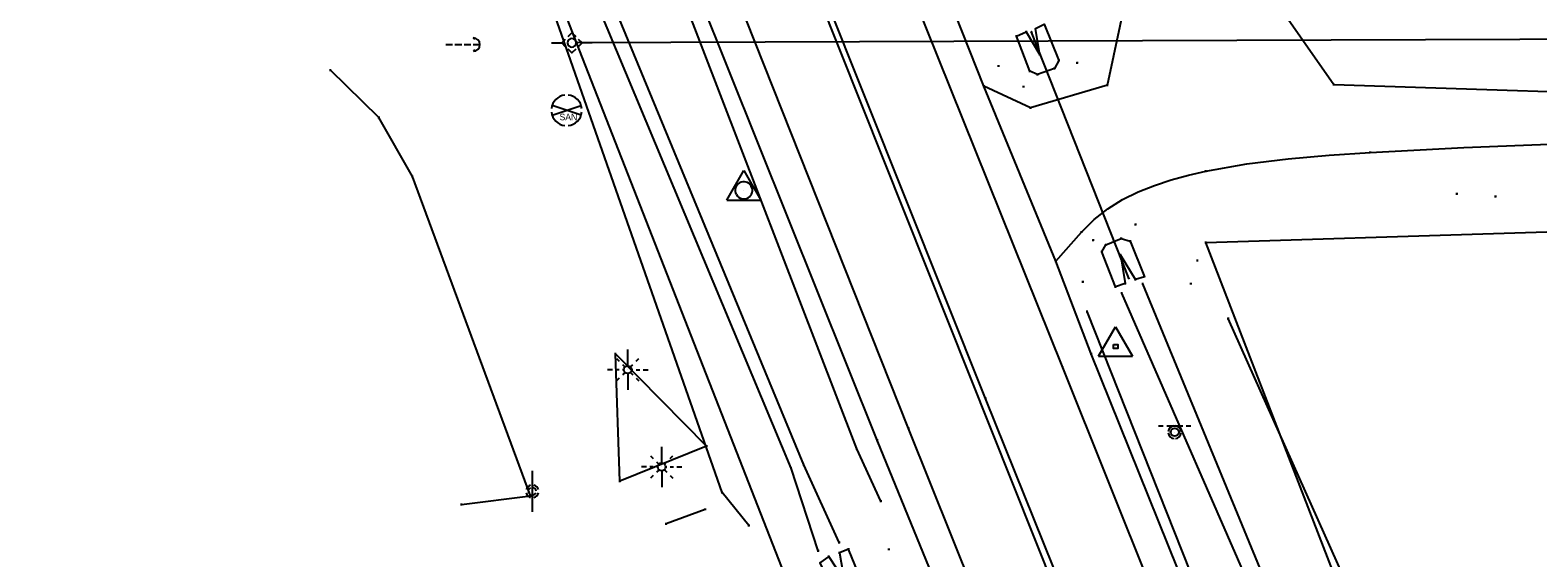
# Model space of a CAD drawing. Extents: x 1954856 to 2011933, y 399149 to 426294.
# Drawn here: x 2004038.2 to 2004259.6, y 409894.5 to 409972 of the extents above; entities that cross this region are included whole.
import ezdxf

# ---------------------------------------------------------------- set-up
doc = ezdxf.new("R2010")
doc.units = 0
for name, color, linetype in [('BankMent_ep', 7, 'Continuous'), ('BaselineSurvey', 7, 'Continuous'), ('Driveway_ep', 7, 'Continuous'), ('ElecAer_ep', 7, 'Continuous'), ('EndTreatMES_ep', 7, 'Continuous'), ('Fence_ep', 7, 'Continuous'), ('FlowLineInvert_ep', 7, 'Continuous'), ('GuyWireAnchor_ep', 7, 'Continuous'), ('MonumentIRC_ep', 7, 'Continuous'), ('MonumentNL_ep', 7, 'Continuous'), ('PavtAsphalt_ep', 7, 'Continuous'), ('PavtAsphaltCrown_ep', 7, 'Continuous'), ('PipeCulvert_ep', 7, 'Continuous'), ('PointLocator_ep', 7, 'Continuous'), ('PoleShared_ep', 7, 'Continuous'), ('ShldrPaved_ep', 7, 'Continuous'), ('SignMulti_ep', 7, 'Continuous'), ('SignSingle_ep', 7, 'Continuous'), ('Sprinkler_ep', 7, 'Continuous'), ('TopoMisc_ep', 7, 'Continuous'), ('TreeLineWoods_ep', 7, 'Continuous'), ('ValveCvrSewer_ep', 7, 'Continuous'), ('WaterFct_ep', 7, 'Continuous')]:
    doc.layers.add(name, color=color, linetype=linetype)

msp = doc.modelspace()

# ---------------------------------------------------------------- linework, layer by layer
at = {"layer": 'BankMent_ep'}
for p, q in [((2004159.58, 409910.52), (2004123.48, 410004.36)), ((2004139.82, 409904.12), (2004107.03, 409997.81)), ((2004232.82, 409831.42), (2004193.41, 409930.68)), ((2004254.24, 409839.9), (2004214.14, 409929.67)), ((2004163.13, 409902.84), (2004159.58, 409910.52)), ((2004143.75, 409899.27), (2004139.82, 409904.12))]:
    msp.add_line(p, q, dxfattribs=at)
for points in [[(2004157.02, 409896.76), (2004151.8, 409908.19), (2004113.49, 410000.86), (2004094.88, 410060.4)], [(2004153.92, 409895.54), (2004149.96, 409907.7), (2004111.48, 409999.81), (2004091.05, 410059.29)], [(2004319.2, 409650.34), (2004281.73, 409743.33), (2004242.69, 409835.04), (2004201.58, 409934.74)], [(2004316.4, 409649.26), (2004278.79, 409741.78), (2004241.68, 409834.55), (2004198.51, 409933.41)]]:
    msp.add_lwpolyline(points, dxfattribs=at)
at = {"layer": 'BaselineSurvey'}
msp.add_line((2004967.71, 407935.04), (2004043.6, 410254.04), dxfattribs=at)
msp.add_line((2004967.71, 407935.04), (2004043.6, 410254.04), dxfattribs=at)
at = {"layer": 'Driveway_ep'}
for p, q in [((2004229.64, 409964), (2004211, 409990.58)), ((2004196.39, 409963.92), (2004201.2, 409986.46)), ((2004188.82, 409938.07), (2004192.59, 409942.35))]:
    msp.add_line(p, q, dxfattribs=at)
for points in [[(2004196.39, 409963.92), (2004185.12, 409960.58), (2004178.25, 409963.76)], [(2004343.45, 409960.26), (2004229.64, 409964)], [(2004192.59, 409942.35), (2004194.43, 409944.19), (2004196.45, 409945.77), (2004198.62, 409947.12), (2004200.91, 409948.26), (2004203.31, 409949.22), (2004205.77, 409950.03), (2004208.29, 409950.71), (2004210.82, 409951.29), (2004216.88, 409952.38), (2004222.92, 409953.13), (2004228.95, 409953.65), (2004234.98, 409954.04), (2004248.72, 409954.77), (2004262.49, 409955.3), (2004276.29, 409955.58), (2004290.12, 409955.59), (2004303.98, 409955.28), (2004317.85, 409954.61), (2004331.74, 409953.53), (2004345.64, 409952.02)]]:
    msp.add_lwpolyline(points, dxfattribs=at)
at = {"layer": 'ElecAer_ep'}
for points in [[(2004118.46, 409970.19), (2004017.81, 410228.92), (2003963.49, 410214.77)], [(2004235.16, 409671.95), (2004118.46, 409970.19), (2004326.19, 409970.93)]]:
    msp.add_lwpolyline(points, dxfattribs=at)
at = {"layer": 'EndTreatMES_ep'}
for points in [[(2004183.04, 409971.1), (2004184.47, 409971.75), (2004186.49, 409968.39), (2004185.86, 409972.26), (2004187.12, 409972.87), (2004189.27, 409967.55), (2004188.62, 409966.38), (2004186.13, 409965.48), (2004184.99, 409965.99)], [(2004195.58, 409939.47), (2004196.17, 409940.48), (2004198.42, 409941.4), (2004199.73, 409941), (2004201.83, 409935.81), (2004200.51, 409935.38), (2004198.3, 409939), (2004199.01, 409934.8), (2004197.57, 409934.31)], [(2004160.76, 409889.94), (2004158.39, 409895.82), (2004157.04, 409895.25), (2004157.73, 409891.31), (2004155.47, 409894.72), (2004154.19, 409893.82), (2004156.77, 409888.36)]]:
    msp.add_lwpolyline(points, close=True, dxfattribs=at)
at = {"layer": 'Fence_ep'}
msp.add_lwpolyline([(2004101.56, 409902.35), (2004111.69, 409903.61), (2004094.35, 409950.5), (2004089.44, 409959.16), (2004082.31, 409966.12)], dxfattribs=at)
at = {"layer": 'FlowLineInvert_ep'}
for p, q in [((2004185.33, 409971.64), (2004185.15, 409971.81)), ((2004185.33, 409971.81), (2004185.15, 409971.64)), ((2004185.24, 409971.72), (2004185.24, 409971.72)), ((2004199.63, 409935.49), (2004199.46, 409935.66)), ((2004199.63, 409935.66), (2004199.46, 409935.49)), ((2004199.55, 409935.57), (2004199.55, 409935.57))]:
    msp.add_line(p, q, dxfattribs=at)
at = {"layer": 'GuyWireAnchor_ep'}
for p, q in [((2004099.26, 409969.89), (2004100.26, 409969.89)), ((2004100.6, 409969.89), (2004101.6, 409969.89)), ((2004101.93, 409969.89), (2004102.93, 409969.89)), ((2004103.26, 409969.88), (2004104.26, 409969.88)), ((2004103.29, 409970.86), (2004103.48, 409970.66)), ((2004104.26, 409969.88), (2004104.26, 409969.88)), ((2004103.31, 409968.91), (2004103.54, 409969.14))]:
    msp.add_line(p, q, dxfattribs=at)
msp.add_arc((2004103.29, 409969.88), 0.973, 271.14, 90.0059, dxfattribs=at)
at = {"layer": 'MonumentIRC_ep'}
for p, q in [((2004140.51, 409947.05), (2004143.01, 409951.38)), ((2004143.01, 409951.38), (2004145.51, 409947.05)), ((2004140.51, 409947.05), (2004145.51, 409947.05)), ((2004143.01, 409948.49), (2004143.01, 409948.49))]:
    msp.add_line(p, q, dxfattribs=at)
msp.add_arc((2004143.01, 409948.49), 1.26, 209.9294, 209.03, dxfattribs=at)
at = {"layer": 'MonumentNL_ep'}
for p, q in [((2004195.09, 409924.12), (2004197.59, 409928.45)), ((2004197.59, 409928.45), (2004200.09, 409924.12)), ((2004197.59, 409925.56), (2004197.59, 409925.56)), ((2004195.09, 409924.12), (2004200.09, 409924.12))]:
    msp.add_line(p, q, dxfattribs=at)
msp.add_lwpolyline([(2004197.3, 409925.86), (2004197.9, 409925.86), (2004197.9, 409925.26), (2004197.3, 409925.26)], close=True, dxfattribs=at)
at = {"layer": 'PavtAsphalt_ep'}
for p, q in [((2004189.83, 409922.49), (2004152.41, 410015.61)), ((2004167.21, 409913.54), (2004129.98, 410007.16)), ((2004227.23, 409829.25), (2004189.83, 409922.49)), ((2004204.26, 409821.07), (2004167.21, 409913.54))]:
    msp.add_line(p, q, dxfattribs=at)
at = {"layer": 'PavtAsphaltCrown_ep'}
for p, q in [((2004178.49, 409917.94), (2004141.27, 410011.21)), ((2004215.72, 409825.41), (2004178.49, 409917.94))]:
    msp.add_line(p, q, dxfattribs=at)
at = {"layer": 'PipeCulvert_ep'}
msp.add_lwpolyline([(2004199.55, 409935.57), (2004185.24, 409971.72)], dxfattribs=at)
at = {"layer": 'PointLocator_ep'}
for p, q in [((2004184.6, 409971.75), (2004184.35, 409971.75)), ((2004184.47, 409971.62), (2004184.47, 409971.87)), ((2004184.47, 409971.75), (2004184.47, 409971.75)), ((2004118.58, 409970.19), (2004118.33, 409970.19)), ((2004118.46, 409970.07), (2004118.46, 409970.32)), ((2004118.46, 409970.19), (2004118.46, 409970.19)), ((2004183.17, 409971.1), (2004182.92, 409971.1)), ((2004183.04, 409970.97), (2004183.04, 409971.22)), ((2004183.04, 409971.1), (2004183.04, 409971.1)), ((2004186.61, 409968.39), (2004186.36, 409968.39)), ((2004186.49, 409968.26), (2004186.49, 409968.51)), ((2004186.49, 409968.39), (2004186.49, 409968.39)), ((2004189.4, 409967.55), (2004189.15, 409967.55)), ((2004189.27, 409967.43), (2004189.27, 409967.68)), ((2004189.27, 409967.55), (2004189.27, 409967.55)), ((2004192.09, 409967.2), (2004191.84, 409967.2)), ((2004191.97, 409967.07), (2004191.97, 409967.32)), ((2004191.97, 409967.2), (2004191.97, 409967.2)), ((2004082.43, 409966.12), (2004082.18, 409966.12)), ((2004082.31, 409966), (2004082.31, 409966.25)), ((2004082.31, 409966.12), (2004082.31, 409966.12)), ((2004180.53, 409966.74), (2004180.28, 409966.74)), ((2004180.41, 409966.61), (2004180.41, 409966.86)), ((2004180.41, 409966.74), (2004180.41, 409966.74)), ((2004185.11, 409965.99), (2004184.86, 409965.99)), ((2004184.99, 409965.86), (2004184.99, 409966.11)), ((2004184.99, 409965.99), (2004184.99, 409965.99)), ((2004186.26, 409965.48), (2004186.01, 409965.48)), ((2004186.13, 409965.36), (2004186.13, 409965.61)), ((2004186.13, 409965.48), (2004186.13, 409965.48)), ((2004188.74, 409966.38), (2004188.49, 409966.38)), ((2004188.62, 409966.25), (2004188.62, 409966.5)), ((2004188.62, 409966.38), (2004188.62, 409966.38)), ((2004178.38, 409963.76), (2004178.13, 409963.76)), ((2004178.25, 409963.63), (2004178.25, 409963.88)), ((2004178.25, 409963.76), (2004178.25, 409963.76)), ((2004184.21, 409963.7), (2004183.96, 409963.7)), ((2004184.08, 409963.57), (2004184.08, 409963.82)), ((2004184.08, 409963.7), (2004184.08, 409963.7)), ((2004196.51, 409963.92), (2004196.26, 409963.92)), ((2004196.39, 409963.79), (2004196.39, 409964.04)), ((2004196.39, 409963.92), (2004196.39, 409963.92)), ((2004229.76, 409964), (2004229.51, 409964)), ((2004229.64, 409963.87), (2004229.64, 409964.12)), ((2004229.64, 409964), (2004229.64, 409964)), ((2004185.25, 409960.58), (2004185, 409960.58)), ((2004185.12, 409960.46), (2004185.12, 409960.71)), ((2004185.12, 409960.58), (2004185.12, 409960.58)), ((2004089.56, 409959.16), (2004089.31, 409959.16)), ((2004089.44, 409959.04), (2004089.44, 409959.29)), ((2004089.44, 409959.16), (2004089.44, 409959.16)), ((2004235.1, 409954.04), (2004234.85, 409954.04)), ((2004234.98, 409953.92), (2004234.98, 409954.17)), ((2004234.98, 409954.04), (2004234.98, 409954.04)), ((2004094.47, 409950.5), (2004094.22, 409950.5)), ((2004094.35, 409950.38), (2004094.35, 409950.63)), ((2004094.35, 409950.5), (2004094.35, 409950.5)), ((2004210.95, 409951.29), (2004210.7, 409951.29)), ((2004210.82, 409951.16), (2004210.82, 409951.41)), ((2004210.82, 409951.29), (2004210.82, 409951.29)), ((2004247.82, 409947.95), (2004247.57, 409947.95)), ((2004247.7, 409947.82), (2004247.7, 409948.07)), ((2004247.7, 409947.95), (2004247.7, 409947.95)), ((2004253.5, 409947.57), (2004253.25, 409947.57)), ((2004253.38, 409947.45), (2004253.38, 409947.7)), ((2004253.38, 409947.57), (2004253.38, 409947.57)), ((2004200.66, 409943.45), (2004200.41, 409943.45)), ((2004200.54, 409943.32), (2004200.54, 409943.57)), ((2004200.54, 409943.45), (2004200.54, 409943.45)), ((2004192.72, 409942.35), (2004192.47, 409942.35)), ((2004192.59, 409942.23), (2004192.59, 409942.48)), ((2004192.59, 409942.35), (2004192.59, 409942.35)), ((2004194.44, 409941.16), (2004194.19, 409941.16)), ((2004194.32, 409941.03), (2004194.32, 409941.28)), ((2004194.32, 409941.16), (2004194.32, 409941.16)), ((2004196.29, 409940.48), (2004196.04, 409940.48)), ((2004196.17, 409940.35), (2004196.17, 409940.6)), ((2004196.17, 409940.48), (2004196.17, 409940.48)), ((2004198.54, 409941.4), (2004198.29, 409941.4)), ((2004198.42, 409941.28), (2004198.42, 409941.53)), ((2004198.42, 409941.4), (2004198.42, 409941.4)), ((2004199.86, 409941), (2004199.61, 409941)), ((2004199.73, 409940.88), (2004199.73, 409941.13)), ((2004199.73, 409941), (2004199.73, 409941)), ((2004210.95, 409940.82), (2004210.7, 409940.82)), ((2004210.82, 409940.69), (2004210.82, 409940.94)), ((2004210.82, 409940.82), (2004210.82, 409940.82)), ((2004188.82, 409937.94), (2004188.82, 409938.19)), ((2004195.7, 409939.47), (2004195.45, 409939.47)), ((2004195.58, 409939.34), (2004195.58, 409939.59)), ((2004195.58, 409939.47), (2004195.58, 409939.47)), ((2004198.43, 409939), (2004198.18, 409939)), ((2004198.3, 409938.88), (2004198.3, 409939.13)), ((2004198.3, 409939), (2004198.3, 409939)), ((2004209.74, 409938.17), (2004209.49, 409938.17)), ((2004209.61, 409938.05), (2004209.61, 409938.3)), ((2004209.61, 409938.17), (2004209.61, 409938.17)), ((2004188.95, 409938.07), (2004188.7, 409938.07)), ((2004188.82, 409938.07), (2004188.82, 409938.07)), ((2004192.92, 409935.06), (2004192.67, 409935.06)), ((2004192.8, 409934.93), (2004192.8, 409935.18)), ((2004192.8, 409935.06), (2004192.8, 409935.06)), ((2004197.69, 409934.31), (2004197.44, 409934.31)), ((2004197.57, 409934.18), (2004197.57, 409934.43)), ((2004197.57, 409934.31), (2004197.57, 409934.31)), ((2004199.13, 409934.8), (2004198.88, 409934.8)), ((2004199.01, 409934.67), (2004199.01, 409934.92)), ((2004199.01, 409934.8), (2004199.01, 409934.8)), ((2004200.63, 409935.38), (2004200.38, 409935.38)), ((2004200.51, 409935.26), (2004200.51, 409935.51)), ((2004200.51, 409935.38), (2004200.51, 409935.38)), ((2004201.71, 409934.74), (2004201.46, 409934.74)), ((2004201.58, 409934.62), (2004201.58, 409934.87)), ((2004201.58, 409934.74), (2004201.58, 409934.74)), ((2004201.95, 409935.81), (2004201.7, 409935.81)), ((2004201.83, 409935.69), (2004201.83, 409935.94)), ((2004201.83, 409935.81), (2004201.83, 409935.81)), ((2004208.77, 409934.77), (2004208.52, 409934.77)), ((2004208.64, 409934.64), (2004208.64, 409934.89)), ((2004208.64, 409934.77), (2004208.64, 409934.77)), ((2004198.63, 409933.41), (2004198.38, 409933.41)), ((2004198.51, 409933.28), (2004198.51, 409933.53)), ((2004198.51, 409933.41), (2004198.51, 409933.41)), ((2004193.53, 409930.68), (2004193.28, 409930.68)), ((2004193.41, 409930.56), (2004193.41, 409930.81)), ((2004193.41, 409930.68), (2004193.41, 409930.68)), ((2004214.27, 409929.67), (2004214.02, 409929.67)), ((2004214.14, 409929.54), (2004214.14, 409929.79)), ((2004214.14, 409929.67), (2004214.14, 409929.67)), ((2004124.28, 409924.47), (2004124.03, 409924.47)), ((2004124.16, 409924.34), (2004124.16, 409924.59)), ((2004124.16, 409924.47), (2004124.16, 409924.47)), ((2004194.14, 409924.47), (2004193.89, 409924.47)), ((2004194.02, 409924.34), (2004194.02, 409924.59)), ((2004194.02, 409924.47), (2004194.02, 409924.47)), ((2004189.95, 409922.49), (2004189.7, 409922.49)), ((2004189.83, 409922.36), (2004189.83, 409922.61)), ((2004189.83, 409922.49), (2004189.83, 409922.49)), ((2004178.62, 409917.94), (2004178.37, 409917.94)), ((2004178.49, 409917.81), (2004178.49, 409918.06)), ((2004178.49, 409917.94), (2004178.49, 409917.94)), ((2004162.73, 409911.8), (2004162.48, 409911.8)), ((2004162.61, 409911.67), (2004162.61, 409911.92)), ((2004162.61, 409911.8), (2004162.61, 409911.8)), ((2004167.34, 409913.54), (2004167.09, 409913.54)), ((2004167.21, 409913.41), (2004167.21, 409913.66)), ((2004167.21, 409913.54), (2004167.21, 409913.54)), ((2004137.67, 409910.92), (2004137.42, 409910.92)), ((2004137.55, 409910.79), (2004137.55, 409911.04)), ((2004137.55, 409910.92), (2004137.55, 409910.92)), ((2004159.71, 409910.52), (2004159.46, 409910.52)), ((2004159.58, 409910.4), (2004159.58, 409910.65)), ((2004159.58, 409910.52), (2004159.58, 409910.52)), ((2004150.08, 409907.7), (2004149.83, 409907.7)), ((2004149.96, 409907.58), (2004149.96, 409907.83)), ((2004149.96, 409907.7), (2004149.96, 409907.7)), ((2004151.93, 409908.19), (2004151.68, 409908.19)), ((2004151.8, 409908.06), (2004151.8, 409908.31)), ((2004151.8, 409908.19), (2004151.8, 409908.19)), ((2004124.96, 409905.78), (2004124.71, 409905.78)), ((2004124.83, 409905.66), (2004124.83, 409905.91)), ((2004124.83, 409905.78), (2004124.83, 409905.78)), ((2004111.82, 409903.61), (2004111.57, 409903.61)), ((2004111.69, 409903.49), (2004111.69, 409903.74)), ((2004111.69, 409903.61), (2004111.69, 409903.61)), ((2004139.94, 409904.12), (2004139.69, 409904.12)), ((2004139.82, 409904), (2004139.82, 409904.25)), ((2004139.82, 409904.12), (2004139.82, 409904.12)), ((2004163.26, 409902.84), (2004163.01, 409902.84)), ((2004163.13, 409902.72), (2004163.13, 409902.97)), ((2004163.13, 409902.84), (2004163.13, 409902.84)), ((2004101.68, 409902.35), (2004101.43, 409902.35)), ((2004101.56, 409902.22), (2004101.56, 409902.47)), ((2004101.56, 409902.35), (2004101.56, 409902.35)), ((2004137.46, 409901.65), (2004137.21, 409901.65)), ((2004137.33, 409901.53), (2004137.33, 409901.78)), ((2004137.33, 409901.65), (2004137.33, 409901.65)), ((2004131.73, 409899.5), (2004131.48, 409899.5)), ((2004131.6, 409899.38), (2004131.6, 409899.62)), ((2004131.6, 409899.5), (2004131.6, 409899.5)), ((2004143.88, 409899.27), (2004143.63, 409899.27)), ((2004143.75, 409899.14), (2004143.75, 409899.39)), ((2004143.75, 409899.27), (2004143.75, 409899.27)), ((2004157.15, 409896.76), (2004156.9, 409896.76)), ((2004157.02, 409896.64), (2004157.02, 409896.89)), ((2004157.02, 409896.76), (2004157.02, 409896.76)), ((2004154.05, 409895.54), (2004153.8, 409895.54)), ((2004153.92, 409895.42), (2004153.92, 409895.67)), ((2004153.92, 409895.54), (2004153.92, 409895.54)), ((2004155.59, 409894.72), (2004155.34, 409894.72)), ((2004155.47, 409894.59), (2004155.47, 409894.84)), ((2004155.47, 409894.72), (2004155.47, 409894.72)), ((2004157.16, 409895.25), (2004156.91, 409895.25)), ((2004157.04, 409895.12), (2004157.04, 409895.38)), ((2004157.04, 409895.25), (2004157.04, 409895.25)), ((2004158.51, 409895.82), (2004158.26, 409895.82)), ((2004158.39, 409895.7), (2004158.39, 409895.95)), ((2004158.39, 409895.82), (2004158.39, 409895.82)), ((2004164.45, 409895.77), (2004164.2, 409895.77)), ((2004164.32, 409895.65), (2004164.32, 409895.9)), ((2004164.32, 409895.77), (2004164.32, 409895.77))]:
    msp.add_line(p, q, dxfattribs=at)
at = {"layer": 'PoleShared_ep'}
for p, q in [((2004114.78, 409970.13), (2004116.28, 409970.13)), ((2004116.28, 409970.13), (2004116.85, 409970.7)), ((2004116.85, 409969.57), (2004116.28, 409970.13)), ((2004117.77, 409970.13), (2004117.77, 409970.13)), ((2004120.76, 409970.13), (2004119.26, 409970.13))]:
    msp.add_line(p, q, dxfattribs=at)
for points in [[(2004117.21, 409971.06), (2004117.77, 409971.62), (2004118.34, 409971.05)], [(2004118.34, 409969.21), (2004117.77, 409968.65), (2004117.2, 409969.21)], [(2004118.69, 409970.7), (2004119.26, 409970.13), (2004118.69, 409969.57)]]:
    msp.add_lwpolyline(points, dxfattribs=at)
for start, end in [(90, 270), (270, 90)]:
    msp.add_arc((2004117.77, 409970.13), 0.625, start, end, dxfattribs=at)
at = {"layer": 'ShldrPaved_ep'}
for p, q in [((2004178.25, 409963.76), (2004156.94, 410017.49)), ((2004162.61, 409911.8), (2004125.2, 410005.08)), ((2004188.82, 409938.07), (2004178.25, 409963.76)), ((2004194.02, 409924.47), (2004188.82, 409938.07)), ((2004231.74, 409830.81), (2004194.02, 409924.47)), ((2004170.7, 409891.96), (2004162.61, 409911.8))]:
    msp.add_line(p, q, dxfattribs=at)
at = {"layer": 'SignMulti_ep'}
msp.add_lwpolyline([(2004137.33, 409901.65), (2004131.6, 409899.5)], dxfattribs=at)
at = {"layer": 'SignSingle_ep'}
for p, q in [((2004203.9, 409913.93), (2004204.6, 409913.93)), ((2004205.1, 409913.93), (2004207.45, 409913.93)), ((2004207.95, 409913.93), (2004208.65, 409913.93)), ((2004206.28, 409912.98), (2004206.28, 409912.98))]:
    msp.add_line(p, q, dxfattribs=at)
msp.add_circle((2004206.28, 409912.98), 0.594, dxfattribs=at)
for start, end in [(96.0423, 173.9577), (6.0423, 83.9577), (186.0423, 263.9577), (276.0423, 353.9577)]:
    msp.add_arc((2004206.28, 409912.98), 0.95, start, end, dxfattribs=at)
at = {"layer": 'Sprinkler_ep'}
for p, q in [((2004125.97, 409922.73), (2004125.97, 409925.13)), ((2004124.33, 409923.8), (2004124.72, 409923.41)), ((2004125.22, 409922.9), (2004125.56, 409922.56)), ((2004126.39, 409922.55), (2004126.72, 409922.89)), ((2004127.22, 409923.4), (2004127.61, 409923.8)), ((2004123.72, 409922.15), (2004123, 409922.15)), ((2004124.72, 409922.15), (2004124.22, 409922.15)), ((2004124.72, 409920.89), (2004124.33, 409920.51)), ((2004125.4, 409922.15), (2004125.22, 409922.15)), ((2004125.58, 409921.73), (2004125.22, 409921.38)), ((2004125.97, 409922.15), (2004125.97, 409922.15)), ((2004125.97, 409921.58), (2004125.97, 409919.18)), ((2004126.38, 409921.75), (2004126.72, 409921.4)), ((2004126.55, 409922.15), (2004126.72, 409922.15)), ((2004127.22, 409922.15), (2004127.72, 409922.15)), ((2004127.22, 409920.9), (2004127.61, 409920.51)), ((2004128.22, 409922.15), (2004128.95, 409922.15)), ((2004129.31, 409909.52), (2004129.7, 409909.13)), ((2004130.95, 409908.45), (2004130.95, 409910.85)), ((2004132.2, 409909.12), (2004132.59, 409909.52)), ((2004128.7, 409907.88), (2004127.98, 409907.88)), ((2004129.7, 409907.88), (2004129.2, 409907.88)), ((2004130.2, 409908.63), (2004130.54, 409908.28)), ((2004130.38, 409907.88), (2004130.2, 409907.88)), ((2004130.56, 409907.46), (2004130.2, 409907.11)), ((2004130.95, 409907.88), (2004130.95, 409907.88)), ((2004130.95, 409907.3), (2004130.95, 409904.9)), ((2004131.36, 409907.47), (2004131.7, 409907.13)), ((2004131.37, 409908.27), (2004131.7, 409908.61)), ((2004131.53, 409907.88), (2004131.7, 409907.88)), ((2004132.2, 409907.88), (2004132.7, 409907.88)), ((2004133.2, 409907.88), (2004133.93, 409907.88)), ((2004129.7, 409906.62), (2004129.31, 409906.23)), ((2004132.2, 409906.62), (2004132.59, 409906.23))]:
    msp.add_line(p, q, dxfattribs=at)
for centre in [(2004125.97, 409922.15), (2004130.95, 409907.88)]:
    msp.add_circle(centre, 0.575, dxfattribs=at)
at = {"layer": 'TopoMisc_ep'}
msp.add_lwpolyline([(2004124.16, 409924.47), (2004137.55, 409910.92), (2004124.83, 409905.78)], close=True, dxfattribs=at)
at = {"layer": 'TreeLineWoods_ep'}
msp.add_lwpolyline([(2004324.47, 409652.8), (2004286.49, 409744.99), (2004250.47, 409838.3), (2004210.82, 409940.82), (2004342.27, 409944.92)], dxfattribs=at)
at = {"layer": 'ValveCvrSewer_ep'}
for p, q in [((2004114.86, 409959.51), (2004119.13, 409960.94)), ((2004119.13, 409959.51), (2004114.86, 409960.94)), ((2004116.99, 409960.23), (2004116.99, 409960.23))]:
    msp.add_line(p, q, dxfattribs=at)
for start, end in [(96.3794, 173.6206), (6.3794, 83.6206), (186.3794, 263.6206), (276.3794, 353.6206)]:
    msp.add_arc((2004116.99, 409960.23), 2.25, start, end, dxfattribs=at)
at = {"layer": 'WaterFct_ep'}
for p, q in [((2004111.95, 409907.3), (2004111.95, 409901.3)), ((2004111.95, 409904.3), (2004111.95, 409904.3))]:
    msp.add_line(p, q, dxfattribs=at)
for radius, start, end in [(0.937, 105.466, 164.534), (0.937, 15.466, 74.534), (0.937, 195.466, 254.534), (0.562, 180, 243.6122), (0.562, 116.3878, 153.6122), (0.562, 0, 90), (0.562, 270, 333.6122), (0.937, 285.466, 344.534)]:
    msp.add_arc((2004111.95, 409904.3), radius, start, end, dxfattribs=at)

# ---------------------------------------------------------------- texts
at = {"layer": 'ValveCvrSewer_ep'}
msp.add_text('SAN', height=0.95, dxfattribs=at).set_placement((2004115.95, 409958.78))

doc.saveas('drawing.dxf')
